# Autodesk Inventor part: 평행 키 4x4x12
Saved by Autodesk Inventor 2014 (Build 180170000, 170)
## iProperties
Created: 2026-08
Part Number: 평행 키 4x4x12
Material: 일반
Document SubType Name: Modeling
Designer: dg
Density: 1 g/cm^3
Appearance: 기본값
Author: dg
Author: jhkim
Description: 키 및 해당 키홈
Creation Date: 2026-07-31
Sending System: Autodesk Inventor 2027
Preprocessor: ST-DEVELOPER v20.1
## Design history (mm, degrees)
node "평행 키 4x4x121"
body "Solid1"
node "기준1"
